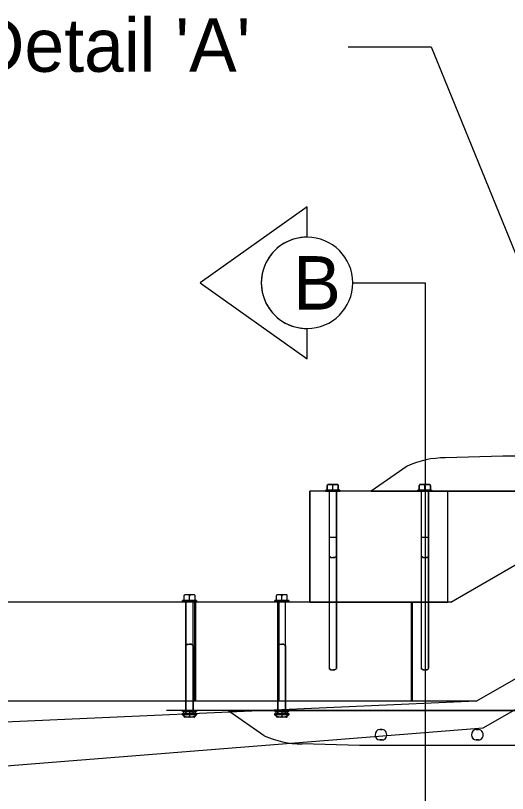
# Model space of a CAD drawing. Extents: x -2137026 to -2131464, y -2138478 to -2136524.
# Drawn here: x -2136885.9 to -2136746.1, y -2137708.2 to -2137486.9 of the extents above; entities that cross this region are included whole.
import ezdxf

# ---------------------------------------------------------------- set-up
doc = ezdxf.new("R2010")
doc.units = 0
for name, color, linetype in [('conPaving', 7, 'Continuous'), ('Level 2', 7, 'Continuous'), ('Level 3', 7, 'Continuous'), ('Level 9', 7, 'Continuous')]:
    doc.layers.add(name, color=color, linetype=linetype)

msp = doc.modelspace()

# ---------------------------------------------------------------- linework, layer by layer
at = {"layer": 'conPaving'}
for p, q in [((-2136747.4, -2137612.31), (-2136763.71, -2137612.74)), ((-2136462.32, -2137612.31), (-2136747.4, -2137612.31)), ((-2136774.55, -2137615.07), (-2136784.8, -2137622.22)), ((-2136797.32, -2137620.66), (-2136797.32, -2137621.92)), ((-2136795.45, -2137620.35), (-2136797.04, -2137620.35)), ((-2136794.42, -2137620.35), (-2136795.45, -2137620.35)), ((-2136794.14, -2137621.92), (-2136794.14, -2137620.66)), ((-2136797.32, -2137621.92), (-2136797.72, -2137621.92)), ((-2136797.72, -2137621.92), (-2136797.72, -2137622.22)), ((-2136797.72, -2137622.22), (-2136796.79, -2137622.22)), ((-2136796.79, -2137622.22), (-2136796.79, -2137640.7)), ((-2136794.67, -2137640.7), (-2136794.67, -2137622.22)), ((-2136794.67, -2137622.22), (-2136793.74, -2137622.22)), ((-2136793.74, -2137621.92), (-2136794.14, -2137621.92)), ((-2136793.74, -2137622.22), (-2136793.74, -2137621.92)), ((-2136784.8, -2137622.22), (-2136770.58, -2137622.22)), ((-2136770.58, -2137622.22), (-2136770.58, -2137640.7)), ((-2136768.45, -2137640.7), (-2136768.45, -2137622.22)), ((-2136768.45, -2137622.22), (-2136441.26, -2137622.22)), ((-2136796.79, -2137635.4), (-2136796.79, -2137672.69)), ((-2136794.67, -2137635.4), (-2136796.79, -2137635.4)), ((-2136794.67, -2137672.69), (-2136794.67, -2137635.4)), ((-2136770.58, -2137635.4), (-2136770.58, -2137672.69)), ((-2136768.45, -2137635.4), (-2136770.58, -2137635.4)), ((-2136768.45, -2137672.69), (-2136768.45, -2137635.4)), ((-2136796.79, -2137640.7), (-2136796.26, -2137641.09)), ((-2136795.2, -2137641.09), (-2136794.67, -2137640.7)), ((-2136770.58, -2137640.7), (-2136770.05, -2137641.09)), ((-2136768.99, -2137641.09), (-2136768.45, -2137640.7)), ((-2136796.26, -2137641.09), (-2136795.73, -2137641.09)), ((-2136795.73, -2137641.09), (-2136795.2, -2137641.09)), ((-2136770.05, -2137641.09), (-2136769.52, -2137641.09)), ((-2136769.52, -2137641.09), (-2136768.99, -2137641.09)), ((-2136838.04, -2137652.06), (-2136838.04, -2137653.32)), ((-2136836.17, -2137651.75), (-2136837.76, -2137651.75)), ((-2136835.14, -2137651.75), (-2136836.17, -2137651.75)), ((-2136834.86, -2137653.32), (-2136834.86, -2137652.06)), ((-2136811.83, -2137652.06), (-2136811.83, -2137653.32)), ((-2136809.95, -2137651.75), (-2136811.54, -2137651.75)), ((-2136808.93, -2137651.75), (-2136809.95, -2137651.75)), ((-2136808.64, -2137653.32), (-2136808.64, -2137652.06)), ((-2136838.04, -2137653.32), (-2136838.44, -2137653.32)), ((-2136838.44, -2137653.32), (-2136838.44, -2137653.61)), ((-2136838.44, -2137653.61), (-2136837.51, -2137653.61)), ((-2136837.51, -2137653.61), (-2136837.51, -2137685.53)), ((-2136835.39, -2137685.53), (-2136835.39, -2137653.61)), ((-2136835.39, -2137653.61), (-2136834.46, -2137653.61)), ((-2136834.46, -2137653.32), (-2136834.86, -2137653.32)), ((-2136834.46, -2137653.61), (-2136834.46, -2137653.32)), ((-2136811.83, -2137653.32), (-2136812.23, -2137653.32)), ((-2136812.23, -2137653.32), (-2136812.23, -2137653.61)), ((-2136812.23, -2137653.61), (-2136811.3, -2137653.61)), ((-2136811.3, -2137653.61), (-2136811.3, -2137685.53)), ((-2136809.17, -2137685.53), (-2136809.17, -2137653.61)), ((-2136809.17, -2137653.61), (-2136808.24, -2137653.61)), ((-2136808.24, -2137653.32), (-2136808.64, -2137653.32)), ((-2136808.24, -2137653.61), (-2136808.24, -2137653.32)), ((-2136837.51, -2137666.16), (-2136836.98, -2137665.78)), ((-2136837.51, -2137684.65), (-2136837.51, -2137666.16)), ((-2136836.98, -2137665.78), (-2136836.45, -2137665.78)), ((-2136836.45, -2137665.78), (-2136835.92, -2137665.78)), ((-2136835.92, -2137665.78), (-2136835.39, -2137666.16)), ((-2136835.39, -2137666.16), (-2136835.39, -2137684.65)), ((-2136811.3, -2137666.16), (-2136810.77, -2137665.78)), ((-2136811.3, -2137684.65), (-2136811.3, -2137666.16)), ((-2136810.77, -2137665.78), (-2136810.24, -2137665.78)), ((-2136810.24, -2137665.78), (-2136809.7, -2137665.78)), ((-2136809.7, -2137665.78), (-2136809.17, -2137666.16)), ((-2136809.17, -2137666.16), (-2136809.17, -2137684.65)), ((-2136796.79, -2137672.69), (-2136796.26, -2137673.07)), ((-2136796.26, -2137673.07), (-2136795.73, -2137673.07)), ((-2136795.73, -2137673.07), (-2136795.2, -2137673.07)), ((-2136795.2, -2137673.07), (-2136794.67, -2137672.69)), ((-2136770.58, -2137672.69), (-2136770.05, -2137673.07)), ((-2136770.05, -2137673.07), (-2136769.52, -2137673.07)), ((-2136769.52, -2137673.07), (-2136768.99, -2137673.07)), ((-2136768.99, -2137673.07), (-2136768.45, -2137672.69)), ((-2136838.44, -2137684.95), (-2136838.44, -2137684.65)), ((-2136838.44, -2137684.65), (-2136837.51, -2137684.65)), ((-2136838.04, -2137684.95), (-2136838.44, -2137684.95)), ((-2136838.04, -2137686.21), (-2136838.04, -2137684.95)), ((-2136835.39, -2137684.65), (-2136834.46, -2137684.65)), ((-2136834.46, -2137684.95), (-2136834.86, -2137684.95)), ((-2136834.86, -2137684.95), (-2136834.86, -2137686.21)), ((-2136834.46, -2137684.65), (-2136834.46, -2137684.95)), ((-2136815.27, -2137691.8), (-2136825.52, -2137684.65)), ((-2136825.52, -2137684.65), (-2136811.3, -2137684.65)), ((-2136809.17, -2137684.65), (-2136481.98, -2137684.65)), ((-2136836.17, -2137686.52), (-2136837.76, -2137686.52)), ((-2136837.51, -2137685.53), (-2136835.39, -2137685.53)), ((-2136835.14, -2137686.52), (-2136836.17, -2137686.52)), ((-2136811.3, -2137685.53), (-2136809.17, -2137685.53)), ((-2136781.69, -2137690.05), (-2136782.35, -2137690.05)), ((-2136754.26, -2137690.05), (-2136754.93, -2137690.05)), ((-2136788.12, -2137694.56), (-2136804.43, -2137694.13)), ((-2136782.35, -2137693.02), (-2136781.69, -2137693.02)), ((-2136754.93, -2137693.02), (-2136754.26, -2137693.02)), ((-2136503.04, -2137694.56), (-2136788.12, -2137694.56))]:
    msp.add_line(p, q, dxfattribs=at)
for centre in [(-2136836.45, -2137683.14), (-2136810.24, -2137683.14)]:
    msp.add_arc(centre, 3.35, 233.5244, 306.4756, dxfattribs=at)
for centre, major_axis, ratio, start_param, end_param in [((-2136763.71, -2137638.28), (-25.97, 0), 0.98332, 4.712389, 5.142831), ((-2136797.04, -2137620.66), (0, -0.315), 0.899999, 3.141593, 4.712389), ((-2136794.42, -2137620.66), (0, -0.315), 0.899999, 1.570796, 3.141593), ((-2136837.76, -2137652.06), (0, -0.315), 0.899999, 3.141593, 4.712389), ((-2136835.14, -2137652.06), (0, -0.315), 0.899999, 1.570796, 3.141593), ((-2136811.54, -2137652.06), (0, -0.315), 0.899999, 3.141593, 4.712389), ((-2136808.93, -2137652.06), (0, -0.315), 0.899999, 1.570796, 3.141593), ((-2136837.76, -2137686.21), (0, -0.315), 0.899999, 4.712389, 6.283185), ((-2136835.14, -2137686.21), (0, -0.315), 0.899999, 6.283185, 7.853982), ((-2136804.43, -2137668.59), (-25.97, 0), 0.98332, 1.140354, 1.570796), ((-2136782.35, -2137691.53), (0, -1.49), 0.899999, 3.141593, 6.283185), ((-2136781.69, -2137691.53), (0, -1.49), 0.899999, 0, 3.141593), ((-2136754.93, -2137691.53), (0, -1.49), 0.899999, 3.141593, 6.283185), ((-2136754.26, -2137691.53), (0, -1.49), 0.899999, 0, 3.141593)]:
    msp.add_ellipse(centre, major_axis=major_axis, ratio=ratio, start_param=start_param, end_param=end_param, dxfattribs=at)
at = {"layer": 'Level 2'}
for p, q in [((-2136791.38, -2137495.85), (-2136767.77, -2137495.85)), ((-2136767.77, -2137495.85), (-2136700.29, -2137661.41)), ((-2136790.04, -2137562.96), (-2136769.48, -2137562.96)), ((-2136769.48, -2137562.96), (-2136769.48, -2137752.1)), ((-2136762.17, -2137653.8), (-2136709.66, -2137623.48)), ((-2136754.92, -2137682), (-2136695.64, -2137647.78)), ((-2136762.17, -2137653.8), (-2136937.89, -2137653.8)), ((-2136835, -2137653.8), (-2136835, -2137682)), ((-2136834.78, -2137653.8), (-2136834.78, -2137682)), ((-2136811.25, -2137653.8), (-2136811.25, -2137682)), ((-2136811.03, -2137653.8), (-2136811.03, -2137682)), ((-2136773.4, -2137653.8), (-2136773.4, -2137682)), ((-2136773.18, -2137653.8), (-2136773.18, -2137682)), ((-2136752.91, -2137689.58), (-2136691.85, -2137654.33)), ((-2136754.92, -2137682), (-2136937.89, -2137682)), ((-2136937.69, -2137704.25), (-2136752.91, -2137689.58))]:
    msp.add_line(p, q, dxfattribs=at)
at = {"layer": 'Level 3'}
for p, q in [((-2136803.04, -2137541.29), (-2136833.38, -2137562.96)), ((-2136803.04, -2137549.96), (-2136803.04, -2137541.29)), ((-2136833.38, -2137562.96), (-2136803.04, -2137584.62)), ((-2136803.04, -2137584.62), (-2136803.04, -2137575.96))]:
    msp.add_line(p, q, dxfattribs=at)
for start, end in [(89.9948, 270.0052), (90.0052, 269.9948), (270.0052, 89.9948)]:
    msp.add_arc((-2136803.04, -2137562.96), 13, start, end, dxfattribs=at)
at = {"layer": 'Level 9'}
for p, q in [((-2136462.32, -2137612.31), (-2136747.4, -2137612.31)), ((-2136797.32, -2137620.66), (-2136797.32, -2137621.92)), ((-2136797.32, -2137621.92), (-2136797.32, -2137620.66)), ((-2136797.32, -2137621.92), (-2136797.32, -2137620.66)), ((-2136795.45, -2137620.35), (-2136797.04, -2137620.35)), ((-2136797.04, -2137620.35), (-2136796.01, -2137620.35)), ((-2136797.04, -2137620.35), (-2136796.01, -2137620.35)), ((-2136796.01, -2137620.35), (-2136794.42, -2137620.35)), ((-2136796.01, -2137620.35), (-2136794.42, -2137620.35)), ((-2136795.73, -2137621.92), (-2136795.73, -2137620.66)), ((-2136795.73, -2137621.92), (-2136795.73, -2137620.66)), ((-2136795.73, -2137621.92), (-2136795.73, -2137620.66)), ((-2136794.42, -2137620.35), (-2136795.45, -2137620.35)), ((-2136794.14, -2137621.92), (-2136794.14, -2137620.66)), ((-2136794.14, -2137620.66), (-2136794.14, -2137621.92)), ((-2136794.14, -2137620.66), (-2136794.14, -2137621.92)), ((-2136771.11, -2137620.66), (-2136771.11, -2137621.92)), ((-2136771.11, -2137621.92), (-2136771.11, -2137620.66)), ((-2136771.11, -2137621.92), (-2136771.11, -2137620.66)), ((-2136769.23, -2137620.35), (-2136770.83, -2137620.35)), ((-2136770.83, -2137620.35), (-2136769.8, -2137620.35)), ((-2136770.83, -2137620.35), (-2136769.8, -2137620.35)), ((-2136769.8, -2137620.35), (-2136768.21, -2137620.35)), ((-2136769.8, -2137620.35), (-2136768.21, -2137620.35)), ((-2136769.52, -2137621.92), (-2136769.52, -2137620.66)), ((-2136769.52, -2137621.92), (-2136769.52, -2137620.66)), ((-2136769.52, -2137621.92), (-2136769.52, -2137620.66)), ((-2136768.21, -2137620.35), (-2136769.23, -2137620.35)), ((-2136767.92, -2137621.92), (-2136767.92, -2137620.66)), ((-2136767.92, -2137620.66), (-2136767.92, -2137621.92)), ((-2136767.92, -2137620.66), (-2136767.92, -2137621.92)), ((-2136407.43, -2137622.22), (-2136802.28, -2137622.22)), ((-2136802.28, -2137622.22), (-2136802.28, -2137653.8)), ((-2136762.96, -2137622.22), (-2136802.28, -2137622.22)), ((-2136802.28, -2137653.8), (-2136802.28, -2137622.22)), ((-2136795.73, -2137621.92), (-2136797.72, -2137621.92)), ((-2136797.72, -2137622.22), (-2136797.72, -2137621.92)), ((-2136795.73, -2137621.92), (-2136797.72, -2137621.92)), ((-2136797.72, -2137621.92), (-2136797.72, -2137622.22)), ((-2136795.73, -2137621.92), (-2136797.72, -2137621.92)), ((-2136797.72, -2137621.92), (-2136797.72, -2137622.22)), ((-2136793.74, -2137622.22), (-2136797.72, -2137622.22)), ((-2136797.72, -2137622.22), (-2136793.74, -2137622.22)), ((-2136797.72, -2137622.22), (-2136793.74, -2137622.22)), ((-2136794.14, -2137621.92), (-2136797.32, -2137621.92)), ((-2136797.32, -2137621.92), (-2136794.14, -2137621.92)), ((-2136797.32, -2137621.92), (-2136794.14, -2137621.92)), ((-2136795.73, -2137622.22), (-2136796.79, -2137622.22)), ((-2136796.79, -2137622.22), (-2136796.79, -2137640.7)), ((-2136795.73, -2137621.92), (-2136793.74, -2137621.92)), ((-2136795.73, -2137621.92), (-2136793.74, -2137621.92)), ((-2136795.73, -2137621.92), (-2136793.74, -2137621.92)), ((-2136795.73, -2137622.22), (-2136794.67, -2137622.22)), ((-2136795.73, -2137622.22), (-2136794.67, -2137622.22)), ((-2136794.67, -2137622.22), (-2136794.67, -2137640.7)), ((-2136793.74, -2137621.92), (-2136793.74, -2137622.22)), ((-2136793.74, -2137622.22), (-2136793.74, -2137621.92)), ((-2136793.74, -2137622.22), (-2136793.74, -2137621.92)), ((-2136769.52, -2137621.92), (-2136771.51, -2137621.92)), ((-2136771.51, -2137622.22), (-2136771.51, -2137621.92)), ((-2136769.52, -2137621.92), (-2136771.51, -2137621.92)), ((-2136771.51, -2137621.92), (-2136771.51, -2137622.22)), ((-2136769.52, -2137621.92), (-2136771.51, -2137621.92)), ((-2136771.51, -2137621.92), (-2136771.51, -2137622.22)), ((-2136767.53, -2137622.22), (-2136771.51, -2137622.22)), ((-2136771.51, -2137622.22), (-2136767.53, -2137622.22)), ((-2136771.51, -2137622.22), (-2136767.53, -2137622.22)), ((-2136767.92, -2137621.92), (-2136771.11, -2137621.92)), ((-2136771.11, -2137621.92), (-2136767.92, -2137621.92)), ((-2136771.11, -2137621.92), (-2136767.92, -2137621.92)), ((-2136769.52, -2137622.22), (-2136770.58, -2137622.22)), ((-2136770.58, -2137622.22), (-2136770.58, -2137640.7)), ((-2136769.52, -2137621.92), (-2136767.53, -2137621.92)), ((-2136769.52, -2137621.92), (-2136767.53, -2137621.92)), ((-2136769.52, -2137621.92), (-2136767.53, -2137621.92)), ((-2136769.52, -2137622.22), (-2136768.45, -2137622.22)), ((-2136769.52, -2137622.22), (-2136768.45, -2137622.22)), ((-2136768.45, -2137622.22), (-2136768.45, -2137640.7)), ((-2136767.53, -2137621.92), (-2136767.53, -2137622.22)), ((-2136767.53, -2137622.22), (-2136767.53, -2137621.92)), ((-2136767.53, -2137622.22), (-2136767.53, -2137621.92)), ((-2136762.96, -2137653.8), (-2136762.96, -2137622.22)), ((-2136762.96, -2137653.8), (-2136762.96, -2137622.22)), ((-2136796.79, -2137635.4), (-2136796.79, -2137672.69)), ((-2136794.67, -2137635.4), (-2136794.67, -2137672.69)), ((-2136770.58, -2137635.4), (-2136770.58, -2137672.69)), ((-2136768.45, -2137635.4), (-2136768.45, -2137672.69)), ((-2136796.26, -2137641.09), (-2136796.79, -2137640.7)), ((-2136795.2, -2137641.09), (-2136794.67, -2137640.7)), ((-2136770.05, -2137641.09), (-2136770.58, -2137640.7)), ((-2136768.99, -2137641.09), (-2136768.45, -2137640.7)), ((-2136796.26, -2137641.09), (-2136795.73, -2137641.09)), ((-2136795.2, -2137641.09), (-2136795.73, -2137641.09)), ((-2136770.05, -2137641.09), (-2136769.52, -2137641.09)), ((-2136768.99, -2137641.09), (-2136769.52, -2137641.09)), ((-2136838.04, -2137652.06), (-2136838.04, -2137653.32)), ((-2136836.17, -2137651.75), (-2136837.76, -2137651.75)), ((-2136836.45, -2137653.32), (-2136836.45, -2137652.06)), ((-2136835.14, -2137651.75), (-2136836.17, -2137651.75)), ((-2136834.86, -2137653.32), (-2136834.86, -2137652.06)), ((-2136811.83, -2137652.06), (-2136811.83, -2137653.32)), ((-2136809.95, -2137651.75), (-2136811.54, -2137651.75)), ((-2136810.24, -2137653.32), (-2136810.24, -2137652.06)), ((-2136808.93, -2137651.75), (-2136809.95, -2137651.75)), ((-2136808.64, -2137653.32), (-2136808.64, -2137652.06)), ((-2136836.45, -2137653.32), (-2136838.44, -2137653.32)), ((-2136838.44, -2137653.61), (-2136838.44, -2137653.32)), ((-2136834.46, -2137653.61), (-2136838.44, -2137653.61)), ((-2136834.86, -2137653.32), (-2136838.04, -2137653.32)), ((-2136836.45, -2137653.61), (-2136837.51, -2137653.61)), ((-2136837.51, -2137685.53), (-2136837.51, -2137653.61)), ((-2136836.45, -2137653.32), (-2136834.46, -2137653.32)), ((-2136835.39, -2137685.53), (-2136835.39, -2137653.61)), ((-2136834.46, -2137653.32), (-2136834.46, -2137653.61)), ((-2136810.24, -2137653.32), (-2136812.23, -2137653.32)), ((-2136812.23, -2137653.61), (-2136812.23, -2137653.32)), ((-2136808.24, -2137653.61), (-2136812.23, -2137653.61)), ((-2136808.64, -2137653.32), (-2136811.83, -2137653.32)), ((-2136810.24, -2137653.61), (-2136811.3, -2137653.61)), ((-2136811.3, -2137685.53), (-2136811.3, -2137653.61)), ((-2136810.24, -2137653.32), (-2136808.24, -2137653.32)), ((-2136809.17, -2137685.53), (-2136809.17, -2137653.61)), ((-2136808.24, -2137653.32), (-2136808.24, -2137653.61)), ((-2136802.28, -2137653.8), (-2136762.96, -2137653.8)), ((-2136802.28, -2137653.8), (-2136762.96, -2137653.8)), ((-2136802.28, -2137653.8), (-2136762.96, -2137653.8)), ((-2136836.98, -2137665.78), (-2136837.51, -2137666.16)), ((-2136837.51, -2137684.65), (-2136837.51, -2137666.16)), ((-2136836.98, -2137665.78), (-2136836.45, -2137665.78)), ((-2136835.92, -2137665.78), (-2136836.45, -2137665.78)), ((-2136835.92, -2137665.78), (-2136835.39, -2137666.16)), ((-2136835.39, -2137684.65), (-2136835.39, -2137666.16)), ((-2136810.77, -2137665.78), (-2136811.3, -2137666.16)), ((-2136811.3, -2137684.65), (-2136811.3, -2137666.16)), ((-2136810.77, -2137665.78), (-2136810.24, -2137665.78)), ((-2136809.7, -2137665.78), (-2136810.24, -2137665.78)), ((-2136809.7, -2137665.78), (-2136809.17, -2137666.16)), ((-2136809.17, -2137684.65), (-2136809.17, -2137666.16)), ((-2136796.26, -2137673.07), (-2136796.79, -2137672.69)), ((-2136796.26, -2137673.07), (-2136795.73, -2137673.07)), ((-2136795.2, -2137673.07), (-2136795.73, -2137673.07)), ((-2136795.2, -2137673.07), (-2136794.67, -2137672.69)), ((-2136770.05, -2137673.07), (-2136770.58, -2137672.69)), ((-2136770.05, -2137673.07), (-2136769.52, -2137673.07)), ((-2136768.99, -2137673.07), (-2136769.52, -2137673.07)), ((-2136768.99, -2137673.07), (-2136768.45, -2137672.69)), ((-2136754.92, -2137682), (-2136937.89, -2137690.12)), ((-2136448.15, -2137684.65), (-2136843, -2137684.65)), ((-2136834.46, -2137684.65), (-2136838.44, -2137684.65)), ((-2136838.44, -2137684.65), (-2136838.44, -2137684.95)), ((-2136836.45, -2137684.95), (-2136838.44, -2137684.95)), ((-2136834.86, -2137684.95), (-2136838.04, -2137684.95)), ((-2136838.04, -2137686.21), (-2136838.04, -2137684.95)), ((-2136836.45, -2137684.65), (-2136837.51, -2137684.65)), ((-2136836.45, -2137684.95), (-2136834.46, -2137684.95)), ((-2136836.45, -2137684.95), (-2136836.45, -2137686.21)), ((-2136834.86, -2137684.95), (-2136834.86, -2137686.21)), ((-2136834.46, -2137684.95), (-2136834.46, -2137684.65)), ((-2136808.24, -2137684.65), (-2136812.23, -2137684.65)), ((-2136812.23, -2137684.65), (-2136812.23, -2137684.95)), ((-2136810.24, -2137684.95), (-2136812.23, -2137684.95)), ((-2136808.64, -2137684.95), (-2136811.83, -2137684.95)), ((-2136811.83, -2137686.21), (-2136811.83, -2137684.95)), ((-2136810.24, -2137684.65), (-2136811.3, -2137684.65)), ((-2136810.24, -2137684.95), (-2136808.24, -2137684.95)), ((-2136810.24, -2137684.95), (-2136810.24, -2137686.21)), ((-2136808.64, -2137684.95), (-2136808.64, -2137686.21)), ((-2136808.24, -2137684.95), (-2136808.24, -2137684.65)), ((-2136836.45, -2137685.53), (-2136838.44, -2137685.53)), ((-2136838.44, -2137685.83), (-2136838.44, -2137685.53)), ((-2136834.46, -2137685.83), (-2136838.44, -2137685.83)), ((-2136834.86, -2137685.53), (-2136838.04, -2137685.53)), ((-2136836.17, -2137686.52), (-2136837.76, -2137686.52)), ((-2136836.45, -2137685.83), (-2136837.51, -2137685.83)), ((-2136836.45, -2137685.53), (-2136834.46, -2137685.53)), ((-2136835.14, -2137686.52), (-2136836.17, -2137686.52)), ((-2136834.46, -2137685.53), (-2136834.46, -2137685.83)), ((-2136810.24, -2137685.53), (-2136812.23, -2137685.53)), ((-2136812.23, -2137685.83), (-2136812.23, -2137685.53)), ((-2136808.24, -2137685.83), (-2136812.23, -2137685.83)), ((-2136808.64, -2137685.53), (-2136811.83, -2137685.53)), ((-2136809.95, -2137686.52), (-2136811.54, -2137686.52)), ((-2136810.24, -2137685.83), (-2136811.3, -2137685.83)), ((-2136810.24, -2137685.53), (-2136808.24, -2137685.53)), ((-2136808.93, -2137686.52), (-2136809.95, -2137686.52)), ((-2136808.24, -2137685.53), (-2136808.24, -2137685.83)), ((-2136503.04, -2137694.56), (-2136788.12, -2137694.56))]:
    msp.add_line(p, q, dxfattribs=at)
for points in [[(-2136747.4, -2137612.31), (-2136763.71, -2137612.74)], [(-2136774.55, -2137615.07), (-2136784.8, -2137622.22)], [(-2136815.27, -2137691.8), (-2136825.52, -2137684.65)], [(-2136782.35, -2137690.05), (-2136781.69, -2137690.05)], [(-2136754.93, -2137690.05), (-2136754.26, -2137690.05)], [(-2136788.12, -2137694.56), (-2136804.43, -2137694.13)], [(-2136781.69, -2137693.02), (-2136782.35, -2137693.02)], [(-2136754.26, -2137693.02), (-2136754.93, -2137693.02)]]:
    msp.add_lwpolyline(points, dxfattribs=at)
for centre, major_axis, ratio, start_param, end_param in [((-2136763.71, -2137638.28), (-25.97, 0), 0.98332, 4.712389, 5.142831), ((-2136797.04, -2137620.66), (0, -0.315), 0.899999, 3.141593, 4.712389), ((-2136797.04, -2137620.66), (0, 0.315), 0.899999, 6.283185, 7.853982), ((-2136797.04, -2137620.66), (0, 0.315), 0.899999, 6.283185, 7.853982), ((-2136796.01, -2137620.66), (0, -0.315), 0.899999, 1.570796, 3.141593), ((-2136796.01, -2137620.66), (0, 0.315), 0.899999, 4.712389, 6.283185), ((-2136796.01, -2137620.66), (0, 0.315), 0.899999, 4.712389, 6.283185), ((-2136795.45, -2137620.66), (0, -0.315), 0.899999, 3.141593, 4.712389), ((-2136795.45, -2137620.66), (0, 0.315), 0.899999, 0, 1.570796), ((-2136795.45, -2137620.66), (0, 0.315), 0.899999, 0, 1.570796), ((-2136794.42, -2137620.66), (0, -0.315), 0.899999, 1.570796, 3.141593), ((-2136794.42, -2137620.66), (0, 0.315), 0.899999, 4.712389, 6.283185), ((-2136794.42, -2137620.66), (0, 0.315), 0.899999, 4.712389, 6.283185), ((-2136770.83, -2137620.66), (0, -0.315), 0.899999, 3.141593, 4.712389), ((-2136770.83, -2137620.66), (0, 0.315), 0.899999, 6.283185, 7.853982), ((-2136770.83, -2137620.66), (0, 0.315), 0.899999, 6.283185, 7.853982), ((-2136769.8, -2137620.66), (0, -0.315), 0.899999, 1.570796, 3.141593), ((-2136769.8, -2137620.66), (0, 0.315), 0.899999, 4.712389, 6.283185), ((-2136769.8, -2137620.66), (0, 0.315), 0.899999, 4.712389, 6.283185), ((-2136769.23, -2137620.66), (0, -0.315), 0.899999, 3.141593, 4.712389), ((-2136769.23, -2137620.66), (0, 0.315), 0.899999, 0, 1.570796), ((-2136769.23, -2137620.66), (0, 0.315), 0.899999, 0, 1.570796), ((-2136768.21, -2137620.66), (0, -0.315), 0.899999, 1.570796, 3.141593), ((-2136768.21, -2137620.66), (0, 0.315), 0.899999, 4.712389, 6.283185), ((-2136768.21, -2137620.66), (0, 0.315), 0.899999, 4.712389, 6.283185), ((-2136837.76, -2137652.06), (0, -0.315), 0.899999, 3.141593, 4.712389), ((-2136836.73, -2137652.06), (0, -0.315), 0.899999, 1.570796, 3.141593), ((-2136836.17, -2137652.06), (0, -0.315), 0.899999, 3.141593, 4.712389), ((-2136835.14, -2137652.06), (0, -0.315), 0.899999, 1.570796, 3.141593), ((-2136811.54, -2137652.06), (0, -0.315), 0.899999, 3.141593, 4.712389), ((-2136810.52, -2137652.06), (0, -0.315), 0.899999, 1.570796, 3.141593), ((-2136809.95, -2137652.06), (0, -0.315), 0.899999, 3.141593, 4.712389), ((-2136808.93, -2137652.06), (0, -0.315), 0.899999, 1.570796, 3.141593), ((-2136837.76, -2137686.21), (0, -0.315), 0.899999, 4.712389, 6.283185), ((-2136836.73, -2137686.21), (0, -0.315), 0.899999, 0, 1.570796), ((-2136836.17, -2137686.21), (0, -0.315), 0.899999, 4.712389, 6.283185), ((-2136835.14, -2137686.21), (0, -0.315), 0.899999, 6.283185, 7.853982), ((-2136811.54, -2137686.21), (0, -0.315), 0.899999, 4.712389, 6.283185), ((-2136810.52, -2137686.21), (0, -0.315), 0.899999, 0, 1.570796), ((-2136809.95, -2137686.21), (0, -0.315), 0.899999, 4.712389, 6.283185), ((-2136808.93, -2137686.21), (0, -0.315), 0.899999, 6.283185, 7.853982), ((-2136804.43, -2137668.59), (-25.97, 0), 0.98332, 1.140354, 1.570796), ((-2136782.35, -2137691.53), (0, -1.49), 0.899999, 3.141593, 6.283185), ((-2136781.69, -2137691.53), (0, -1.49), 0.899999, 0, 3.141593), ((-2136754.93, -2137691.53), (0, -1.49), 0.899999, 3.141593, 6.283185), ((-2136754.26, -2137691.53), (0, -1.49), 0.899999, 0, 3.141593)]:
    msp.add_ellipse(centre, major_axis=major_axis, ratio=ratio, start_param=start_param, end_param=end_param, dxfattribs=at)

# ---------------------------------------------------------------- texts
at = {"layer": 'Level 3'}
for s, p in [("See Detail 'A'", (-2136939.89, -2137502.91)), ('B', (-2136806.96, -2137570.56))]:
    msp.add_text(s, height=15.2, dxfattribs=at).set_placement(p)

doc.saveas('drawing.dxf')
